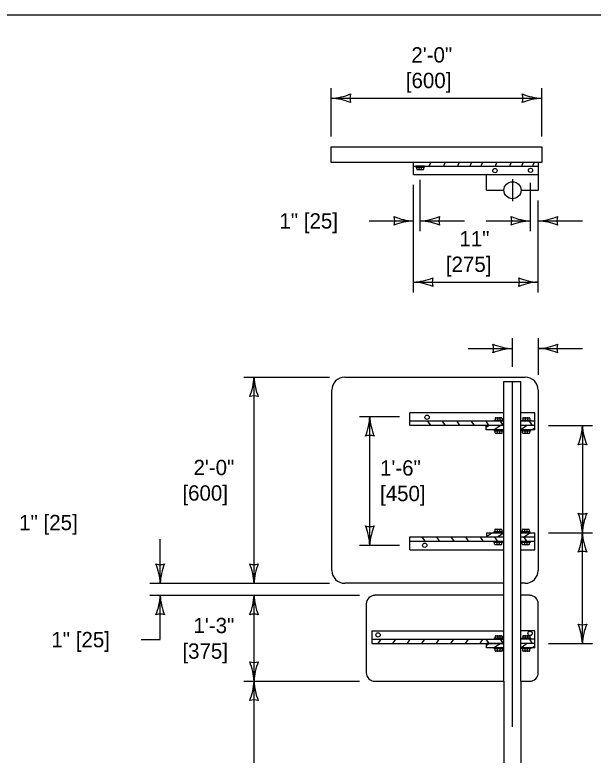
# Model space of a CAD drawing. Extents: x 49991.4 to 50021, y 49987.6 to 50011.4.
# Drawn here: x 50012.618 to 50014.882, y 49996.099 to 49998.999 of the extents above; entities that cross this region are included whole.
import ezdxf

# ---------------------------------------------------------------- set-up
doc = ezdxf.new("R2010")
doc.units = 0
for name, color, linetype in [('Level 1', 7, 'Continuous'), ('Level 2', 7, 'Continuous'), ('Level 3', 7, 'Continuous'), ('Level 4', 7, 'Continuous'), ('Level 5', 7, 'Continuous')]:
    doc.layers.add(name, color=color, linetype=linetype)

msp = doc.modelspace()

# ---------------------------------------------------------------- linework, layer by layer
at = {"layer": 'Level 1'}
for p, q in [((50014.1786, 49998.3732), (50014.1786, 49998.4206)), ((50014.2408, 49998.4065), (50014.2461, 49998.4206)), ((50014.2976, 49998.4065), (50014.3029, 49998.4206)), ((50014.3526, 49998.4065), (50014.358, 49998.4206)), ((50014.4006, 49998.4065), (50014.4059, 49998.4206)), ((50014.4435, 49998.4065), (50014.4489, 49998.4206)), ((50014.5003, 49998.4065), (50014.5057, 49998.4206)), ((50014.5554, 49998.4065), (50014.5607, 49998.4206)), ((50014.6033, 49998.4065), (50014.6087, 49998.4206)), ((50014.6464, 49998.4065), (50014.6518, 49998.4206)), ((50014.6668, 49998.4206), (50014.6668, 49998.3119)), ((50014.1786, 49998.4065), (50014.6668, 49998.4065)), ((50014.1913, 49998.3955), (50014.1913, 49998.4018)), ((50014.1939, 49998.3929), (50014.2165, 49998.3929)), ((50014.2005, 49998.3954), (50014.2005, 49998.4018)), ((50014.2097, 49998.3954), (50014.2097, 49998.4018)), ((50014.219, 49998.3955), (50014.219, 49998.4018)), ((50014.1786, 49998.3732), (50014.4642, 49998.3732)), ((50014.4642, 49998.3732), (50014.6659, 49998.3732)), ((50014.4642, 49998.3119), (50014.4642, 49998.3732)), ((50014.4642, 49998.3119), (50014.5331, 49998.3119)), ((50014.5996, 49998.3119), (50014.6668, 49998.3119)), ((50013.9097, 49997.5797), (50014.6163, 49997.5797)), ((50014.5327, 49996.3886), (50014.5327, 49997.563)), ((50014.5327, 49997.563), (50014.5992, 49997.563)), ((50014.5992, 49996.3886), (50014.5992, 49997.563)), ((50013.8593, 49996.8226), (50013.8593, 49997.5292)), ((50014.6668, 49997.5292), (50014.6668, 49996.8226)), ((50014.5316, 49997.4401), (50014.1645, 49997.4401)), ((50014.1645, 49997.3901), (50014.1645, 49997.4401)), ((50014.6535, 49997.4401), (50014.5993, 49997.4401)), ((50014.6535, 49997.3734), (50014.6535, 49997.4401)), ((50014.5316, 49997.4068), (50014.1645, 49997.4068)), ((50014.2341, 49997.4068), (50014.2454, 49997.3901)), ((50014.2911, 49997.4068), (50014.3023, 49997.3901)), ((50014.3479, 49997.4068), (50014.3591, 49997.3901)), ((50014.4048, 49997.4068), (50014.416, 49997.3901)), ((50014.4617, 49997.4068), (50014.473, 49997.3901)), ((50014.4981, 49997.4181), (50014.4981, 49997.4119)), ((50014.5005, 49997.4206), (50014.5232, 49997.4206)), ((50014.5006, 49997.4206), (50014.5232, 49997.4206)), ((50014.5072, 49997.4206), (50014.5072, 49997.4119)), ((50014.5165, 49997.4206), (50014.5165, 49997.4119)), ((50014.5186, 49997.4068), (50014.5298, 49997.3901)), ((50014.5191, 49997.406), (50014.5288, 49997.3916)), ((50014.5191, 49997.406), (50014.5288, 49997.3916)), ((50014.5257, 49997.4181), (50014.5257, 49997.4119)), ((50014.6535, 49997.4068), (50014.5992, 49997.4068)), ((50014.6064, 49997.4181), (50014.6064, 49997.4119)), ((50014.6088, 49997.4206), (50014.6315, 49997.4206)), ((50014.6089, 49997.4206), (50014.6315, 49997.4206)), ((50014.6155, 49997.4206), (50014.6155, 49997.4119)), ((50014.6248, 49997.4206), (50014.6248, 49997.4119)), ((50014.6324, 49997.4067), (50014.6435, 49997.3901)), ((50014.6324, 49997.4067), (50014.6425, 49997.3916)), ((50014.6324, 49997.4067), (50014.6425, 49997.3916)), ((50014.634, 49997.4181), (50014.634, 49997.4119)), ((50014.4639, 49997.3901), (50014.1645, 49997.3901)), ((50014.5316, 49997.3901), (50014.4639, 49997.3901)), ((50014.4639, 49997.384), (50014.473, 49997.3901)), ((50014.5322, 49997.3901), (50014.4639, 49997.3901)), ((50014.4639, 49997.3734), (50014.4639, 49997.39)), ((50014.5303, 49997.3734), (50014.4639, 49997.3734)), ((50014.4934, 49997.3734), (50014.5181, 49997.3901)), ((50014.6535, 49997.3901), (50014.5985, 49997.3901)), ((50014.6535, 49997.3901), (50014.5985, 49997.3901)), ((50014.6535, 49997.3901), (50014.5992, 49997.3901)), ((50014.5992, 49997.3749), (50014.6212, 49997.3899)), ((50014.6535, 49997.3734), (50014.5993, 49997.3734)), ((50014.6535, 49997.3901), (50014.5998, 49997.3901)), ((50014.6421, 49997.3734), (50014.6535, 49997.381)), ((50014.4989, 49997.3622), (50014.4989, 49997.3684)), ((50014.524, 49997.3596), (50014.5014, 49997.3596)), ((50014.5241, 49997.3596), (50014.5014, 49997.3596)), ((50014.5081, 49997.3596), (50014.5081, 49997.3684)), ((50014.5174, 49997.3596), (50014.5174, 49997.3684)), ((50014.5266, 49997.3622), (50014.5266, 49997.3684)), ((50014.6062, 49997.3621), (50014.6062, 49997.3683)), ((50014.6313, 49997.3595), (50014.6086, 49997.3595)), ((50014.6314, 49997.3595), (50014.6086, 49997.3595)), ((50014.6154, 49997.3595), (50014.6154, 49997.3683)), ((50014.6247, 49997.3595), (50014.6247, 49997.3683)), ((50014.6338, 49997.3621), (50014.6338, 49997.3683)), ((50014.4642, 49996.9704), (50014.4642, 49996.954)), ((50014.4642, 49996.9704), (50014.5309, 49996.9704)), ((50014.488, 49996.97), (50014.4642, 49996.954)), ((50014.4968, 49996.9817), (50014.4968, 49996.9756)), ((50014.4993, 49996.9843), (50014.522, 49996.9843)), ((50014.4994, 49996.9843), (50014.522, 49996.9843)), ((50014.506, 49996.9843), (50014.506, 49996.9756)), ((50014.532, 49996.9692), (50014.5095, 49996.9539)), ((50014.5153, 49996.9843), (50014.5153, 49996.9756)), ((50014.5245, 49996.9817), (50014.5245, 49996.9756)), ((50014.5993, 49996.9704), (50014.6535, 49996.9704)), ((50014.6041, 49996.9816), (50014.6041, 49996.9755)), ((50014.6066, 49996.9842), (50014.6293, 49996.9842)), ((50014.6066, 49996.9842), (50014.6293, 49996.9842)), ((50014.6373, 49996.9705), (50014.6128, 49996.9539)), ((50014.6132, 49996.9842), (50014.6132, 49996.9755)), ((50014.6225, 49996.9842), (50014.6225, 49996.9755)), ((50014.6317, 49996.9816), (50014.6317, 49996.9755)), ((50014.6535, 49996.9037), (50014.6535, 49996.9704)), ((50014.1645, 49996.9037), (50014.1645, 49996.9537)), ((50014.1645, 49996.9537), (50014.4642, 49996.9537)), ((50014.1645, 49996.937), (50014.5323, 49996.937)), ((50014.2117, 49996.9537), (50014.2227, 49996.9376)), ((50014.2686, 49996.9537), (50014.2796, 49996.9376)), ((50014.3254, 49996.9537), (50014.3364, 49996.9376)), ((50014.3824, 49996.9537), (50014.3933, 49996.9376)), ((50014.4393, 49996.9537), (50014.4502, 49996.9376)), ((50014.4393, 49996.9537), (50014.4502, 49996.9376)), ((50014.4642, 49996.9537), (50014.5323, 49996.9537)), ((50014.4961, 49996.9537), (50014.507, 49996.9376)), ((50014.4961, 49996.9537), (50014.507, 49996.9376)), ((50014.4961, 49996.9537), (50014.507, 49996.9376)), ((50014.4961, 49996.9537), (50014.507, 49996.9376)), ((50014.4961, 49996.9537), (50014.507, 49996.9376)), ((50014.4961, 49996.9537), (50014.507, 49996.9376)), ((50014.599, 49996.9537), (50014.6535, 49996.9537)), ((50014.599, 49996.9537), (50014.6523, 49996.9537)), ((50014.599, 49996.9537), (50014.6523, 49996.9537)), ((50014.599, 49996.9537), (50014.6513, 49996.9537)), ((50014.599, 49996.937), (50014.6523, 49996.937)), ((50014.599, 49996.937), (50014.6535, 49996.937)), ((50014.6099, 49996.9537), (50014.6212, 49996.937)), ((50014.6099, 49996.9537), (50014.6208, 49996.9376)), ((50014.6099, 49996.9537), (50014.6208, 49996.9376)), ((50014.4966, 49996.9258), (50014.4966, 49996.9319)), ((50014.5217, 49996.9232), (50014.4991, 49996.9232)), ((50014.5218, 49996.9232), (50014.4991, 49996.9232)), ((50014.5059, 49996.9232), (50014.5059, 49996.9319)), ((50014.5152, 49996.9232), (50014.5152, 49996.9319)), ((50014.5243, 49996.9258), (50014.5243, 49996.9319)), ((50014.6049, 49996.9258), (50014.6049, 49996.9319)), ((50014.63, 49996.9232), (50014.6074, 49996.9232)), ((50014.6301, 49996.9232), (50014.6074, 49996.9232)), ((50014.6142, 49996.9232), (50014.6142, 49996.9319)), ((50014.6235, 49996.9232), (50014.6235, 49996.9319)), ((50014.6326, 49996.9258), (50014.6326, 49996.9319)), ((50014.1645, 49996.9037), (50014.5317, 49996.9037)), ((50014.599, 49996.9037), (50014.6535, 49996.9037)), ((50014.5327, 49996.7722), (50013.9097, 49996.7722)), ((50014.6163, 49996.7722), (50014.5992, 49996.7722)), ((50014.5327, 49996.7251), (50014.0278, 49996.7251)), ((50014.6334, 49996.7251), (50014.5992, 49996.7251)), ((50013.9941, 49996.6914), (50013.9941, 49996.4223)), ((50014.667, 49996.4223), (50014.667, 49996.6914)), ((50014.0155, 49996.5865), (50014.5317, 49996.5865)), ((50014.0155, 49996.5865), (50014.0155, 49996.5366)), ((50014.4982, 49996.5645), (50014.4982, 49996.5583)), ((50014.5006, 49996.567), (50014.5233, 49996.567)), ((50014.5007, 49996.567), (50014.5233, 49996.567)), ((50014.5073, 49996.567), (50014.5073, 49996.5583)), ((50014.5166, 49996.567), (50014.5166, 49996.5583)), ((50014.5258, 49996.5645), (50014.5258, 49996.5583)), ((50014.6536, 49996.5865), (50014.5994, 49996.5865)), ((50014.6065, 49996.5645), (50014.6065, 49996.5583)), ((50014.6089, 49996.567), (50014.6316, 49996.567)), ((50014.609, 49996.567), (50014.6316, 49996.567)), ((50014.6156, 49996.567), (50014.6156, 49996.5583)), ((50014.6249, 49996.567), (50014.6249, 49996.5583)), ((50014.6341, 49996.5645), (50014.6341, 49996.5583)), ((50014.6536, 49996.5198), (50014.6536, 49996.5865)), ((50014.0155, 49996.5533), (50014.5323, 49996.5533)), ((50014.0155, 49996.5366), (50014.464, 49996.5366)), ((50014.0411, 49996.5366), (50014.0524, 49996.5533)), ((50014.098, 49996.5366), (50014.1093, 49996.5533)), ((50014.1549, 49996.5366), (50014.1662, 49996.5533)), ((50014.2117, 49996.5366), (50014.2231, 49996.5533)), ((50014.2686, 49996.5366), (50014.28, 49996.5533)), ((50014.3254, 49996.5366), (50014.3368, 49996.5533)), ((50014.3824, 49996.5366), (50014.3937, 49996.5533)), ((50014.4393, 49996.5366), (50014.4506, 49996.5533)), ((50014.4618, 49996.5533), (50014.4732, 49996.5366)), ((50014.5327, 49996.5366), (50014.464, 49996.5366)), ((50014.464, 49996.5305), (50014.4732, 49996.5366)), ((50014.464, 49996.5366), (50014.5323, 49996.5366)), ((50014.464, 49996.5198), (50014.464, 49996.5365)), ((50014.4965, 49996.5218), (50014.5182, 49996.5366)), ((50014.5186, 49996.5533), (50014.5298, 49996.5366)), ((50014.5186, 49996.5533), (50014.5288, 49996.5381)), ((50014.5192, 49996.5524), (50014.5288, 49996.5381)), ((50014.6536, 49996.5533), (50014.5992, 49996.5533)), ((50014.5992, 49996.5198), (50014.6216, 49996.5366)), ((50014.6536, 49996.5366), (50014.5992, 49996.5366)), ((50014.6536, 49996.5366), (50014.5999, 49996.5366)), ((50014.6325, 49996.5531), (50014.6436, 49996.5366)), ((50014.6325, 49996.5531), (50014.6426, 49996.5381)), ((50014.6325, 49996.5531), (50014.6436, 49996.5366)), ((50014.6536, 49996.5366), (50014.6436, 49996.5366)), ((50014.5327, 49996.5198), (50014.464, 49996.5198)), ((50014.499, 49996.5086), (50014.499, 49996.5148)), ((50014.5241, 49996.5061), (50014.5015, 49996.5061)), ((50014.5242, 49996.5061), (50014.5015, 49996.5061)), ((50014.5082, 49996.5061), (50014.5082, 49996.5148)), ((50014.5175, 49996.5061), (50014.5175, 49996.5148)), ((50014.5267, 49996.5086), (50014.5267, 49996.5148)), ((50014.6536, 49996.5198), (50014.5992, 49996.5198)), ((50014.6063, 49996.5085), (50014.6063, 49996.5147)), ((50014.6314, 49996.506), (50014.6087, 49996.506)), ((50014.6314, 49996.506), (50014.6087, 49996.506)), ((50014.6155, 49996.506), (50014.6155, 49996.5147)), ((50014.6248, 49996.506), (50014.6248, 49996.5147)), ((50014.6339, 49996.5085), (50014.6339, 49996.5147)), ((50014.6422, 49996.5198), (50014.6536, 49996.5275)), ((50014.0278, 49996.3886), (50014.5327, 49996.3886)), ((50014.5327, 49996.3886), (50014.5327, 49994.5009)), ((50014.5992, 49996.3886), (50014.5992, 49994.5009)), ((50014.5992, 49996.3886), (50014.6334, 49996.3886))]:
    msp.add_line(p, q, dxfattribs=at)
for points in [[(49999.3835, 49998.9992), (50016.7501, 49998.9992), (50016.7501, 49987.7988), (49999.3835, 49987.7988)], [(50014.6809, 49998.4822), (50014.6809, 49998.4206), (50013.8568, 49998.4206), (50013.8568, 49998.4822)], [(50014.1886, 49998.4065), (50014.1886, 49998.4018), (50014.2214, 49998.4018), (50014.2214, 49998.4065)], [(50014.4953, 49997.407), (50014.4953, 49997.4117), (50014.5282, 49997.4117), (50014.5282, 49997.407)], [(50014.6036, 49997.407), (50014.6036, 49997.4117), (50014.6365, 49997.4117), (50014.6365, 49997.407)], [(50014.5293, 49997.3732), (50014.5293, 49997.3686), (50014.4964, 49997.3686), (50014.4964, 49997.3732)], [(50014.6366, 49997.3731), (50014.6366, 49997.3685), (50014.6037, 49997.3685), (50014.6037, 49997.3731)], [(50014.4941, 49996.9707), (50014.4941, 49996.9754), (50014.5269, 49996.9754), (50014.5269, 49996.9707)], [(50014.6013, 49996.9706), (50014.6013, 49996.9753), (50014.6342, 49996.9753), (50014.6342, 49996.9706)], [(50014.527, 49996.9368), (50014.527, 49996.9321), (50014.4942, 49996.9321), (50014.4942, 49996.9368)], [(50014.6353, 49996.9368), (50014.6353, 49996.9321), (50014.6025, 49996.9321), (50014.6025, 49996.9368)], [(50014.4954, 49996.5535), (50014.4954, 49996.5581), (50014.5283, 49996.5581), (50014.5283, 49996.5535)], [(50014.6037, 49996.5535), (50014.6037, 49996.5581), (50014.6366, 49996.5581), (50014.6366, 49996.5535)], [(50014.5294, 49996.5196), (50014.5294, 49996.515), (50014.4965, 49996.515), (50014.4965, 49996.5196)], [(50014.6367, 49996.5196), (50014.6367, 49996.5149), (50014.6038, 49996.5149), (50014.6038, 49996.5196)]]:
    msp.add_lwpolyline(points, close=True, dxfattribs=at)
for centre, radius in [((50014.4977, 49998.3891), 0.00843), ((50014.6369, 49998.39), 0.00843), ((50014.5664, 49998.3119), 0.0333), ((50014.2322, 49997.4225), 0.00843), ((50014.2229, 49996.9214), 0.00843), ((50014.04, 49996.5701), 0.00843), ((50014.6352, 49996.576), 0.00843)]:
    msp.add_circle(centre, radius, dxfattribs=at)
for centre, radius, start, end in [((50014.1939, 49998.3954), 0.00257, 180, 270), ((50014.198, 49998.3954), 0.00257, 270, 0), ((50014.2031, 49998.3954), 0.00257, 180, 270), ((50014.2072, 49998.3954), 0.00257, 270, 0), ((50014.2123, 49998.3954), 0.00257, 180, 270), ((50014.2164, 49998.3954), 0.00257, 270, 0), ((50013.9097, 49997.5292), 0.0505, 90, 180), ((50014.6163, 49997.5292), 0.0505, 0, 90), ((50014.5007, 49997.4181), 0.00257, 90, 180), ((50014.5047, 49997.4181), 0.00257, 0, 90), ((50014.5099, 49997.4181), 0.00257, 90, 180), ((50014.5139, 49997.4181), 0.00257, 0, 90), ((50014.5191, 49997.4181), 0.00257, 90, 180), ((50014.5231, 49997.4181), 0.00257, 0, 90), ((50014.609, 49997.4181), 0.00257, 90, 180), ((50014.613, 49997.4181), 0.00257, 0, 90), ((50014.6182, 49997.4181), 0.00257, 90, 180), ((50014.6222, 49997.4181), 0.00257, 0, 90), ((50014.6274, 49997.4181), 0.00257, 90, 180), ((50014.6314, 49997.4181), 0.00257, 0, 90), ((50014.5015, 49997.3622), 0.00257, 180, 270), ((50014.5056, 49997.3622), 0.00257, 270, 0), ((50014.5107, 49997.3622), 0.00257, 180, 270), ((50014.5148, 49997.3622), 0.00257, 270, 0), ((50014.5199, 49997.3622), 0.00257, 180, 270), ((50014.524, 49997.3622), 0.00257, 270, 0), ((50014.6087, 49997.3621), 0.00257, 180, 270), ((50014.6128, 49997.3621), 0.00257, 270, 0), ((50014.618, 49997.3621), 0.00257, 180, 270), ((50014.622, 49997.3621), 0.00257, 270, 0), ((50014.6272, 49997.3621), 0.00257, 180, 270), ((50014.6312, 49997.3621), 0.00257, 270, 0), ((50014.4994, 49996.9818), 0.00257, 90, 180), ((50014.5035, 49996.9818), 0.00257, 0, 90), ((50014.5086, 49996.9818), 0.00257, 90, 180), ((50014.5127, 49996.9818), 0.00257, 0, 90), ((50014.5178, 49996.9818), 0.00257, 90, 180), ((50014.5219, 49996.9818), 0.00257, 0, 90), ((50014.6067, 49996.9817), 0.00257, 90, 180), ((50014.6107, 49996.9817), 0.00257, 0, 90), ((50014.6159, 49996.9817), 0.00257, 90, 180), ((50014.6199, 49996.9817), 0.00257, 0, 90), ((50014.6251, 49996.9817), 0.00257, 90, 180), ((50014.6292, 49996.9817), 0.00257, 0, 90), ((50014.4992, 49996.9257), 0.00257, 180, 270), ((50014.5033, 49996.9257), 0.00257, 270, 0), ((50014.5084, 49996.9257), 0.00257, 180, 270), ((50014.5125, 49996.9257), 0.00257, 270, 0), ((50014.5176, 49996.9257), 0.00257, 180, 270), ((50014.5217, 49996.9257), 0.00257, 270, 0), ((50014.6075, 49996.9257), 0.00257, 180, 270), ((50014.6116, 49996.9257), 0.00257, 270, 0), ((50014.6167, 49996.9257), 0.00257, 180, 270), ((50014.6208, 49996.9257), 0.00257, 270, 0), ((50014.6259, 49996.9257), 0.00257, 180, 270), ((50014.63, 49996.9257), 0.00257, 270, 0), ((50013.9097, 49996.8226), 0.0505, 180, 270), ((50014.6163, 49996.8226), 0.0505, 270, 0), ((50014.0278, 49996.6914), 0.0336, 90, 180), ((50014.6334, 49996.6914), 0.0336, 0, 90), ((50014.5008, 49996.5645), 0.00257, 90, 180), ((50014.5048, 49996.5645), 0.00257, 0, 90), ((50014.51, 49996.5645), 0.00257, 90, 180), ((50014.514, 49996.5645), 0.00257, 0, 90), ((50014.5192, 49996.5645), 0.00257, 90, 180), ((50014.5232, 49996.5645), 0.00257, 0, 90), ((50014.6091, 49996.5645), 0.00257, 90, 180), ((50014.6131, 49996.5645), 0.00257, 0, 90), ((50014.6183, 49996.5645), 0.00257, 90, 180), ((50014.6223, 49996.5645), 0.00257, 0, 90), ((50014.6275, 49996.5645), 0.00257, 90, 180), ((50014.6315, 49996.5645), 0.00257, 0, 90), ((50014.5016, 49996.5086), 0.00257, 180, 270), ((50014.5057, 49996.5086), 0.00257, 270, 0), ((50014.5108, 49996.5086), 0.00257, 180, 270), ((50014.5149, 49996.5086), 0.00257, 270, 0), ((50014.52, 49996.5086), 0.00257, 180, 270), ((50014.5241, 49996.5086), 0.00257, 270, 0), ((50014.6088, 49996.5085), 0.00257, 180, 270), ((50014.6129, 49996.5085), 0.00257, 270, 0), ((50014.6181, 49996.5085), 0.00257, 180, 270), ((50014.6221, 49996.5085), 0.00257, 270, 0), ((50014.6273, 49996.5085), 0.00257, 180, 270), ((50014.6313, 49996.5085), 0.00257, 270, 0), ((50014.0278, 49996.4223), 0.0336, 180, 270), ((50014.6334, 49996.4223), 0.0336, 270, 0)]:
    msp.add_arc(centre, radius, start, end, dxfattribs=at)
at = {"layer": 'Level 3'}
for p, q in [((50013.8568, 49998.5222), (50013.8568, 49998.7122)), ((50014.6809, 49998.5222), (50014.6809, 49998.7122)), ((50013.8568, 49998.6722), (50014.6809, 49998.6722)), ((50014.1786, 49997.9119), (50014.1786, 49998.3332)), ((50014.2052, 49998.1519), (50014.2052, 49998.3528)), ((50014.6372, 49998.1519), (50014.6372, 49998.3416)), ((50014.6668, 49997.9119), (50014.6668, 49998.2719)), ((50014.0052, 49998.1919), (50014.1786, 49998.1919)), ((50014.2052, 49998.1919), (50014.3786, 49998.1919)), ((50014.4638, 49998.1919), (50014.6372, 49998.1919)), ((50014.6668, 49998.1919), (50014.8402, 49998.1919)), ((50014.1786, 49997.9519), (50014.6668, 49997.9519)), ((50014.566, 49997.6197), (50014.566, 49997.732)), ((50014.6668, 49997.732), (50014.6668, 49997.5892)), ((50014.3926, 49997.692), (50014.566, 49997.692)), ((50014.6668, 49997.692), (50014.8402, 49997.692)), ((50013.5146, 49997.5797), (50013.8497, 49997.5797)), ((50013.5546, 49996.7722), (50013.5546, 49997.5797)), ((50013.9678, 49997.4251), (50014.1245, 49997.4251)), ((50014.0078, 49996.9212), (50014.0078, 49997.4251)), ((50014.7068, 49997.3901), (50014.8802, 49997.3901)), ((50014.8402, 49997.3901), (50014.8402, 49996.9704)), ((50014.7068, 49996.9704), (50014.8802, 49996.9704)), ((50014.8402, 49996.5366), (50014.8402, 49996.9704)), ((50013.1874, 49996.7722), (50013.1874, 49996.9456)), ((50013.9678, 49996.9212), (50014.1245, 49996.9212)), ((50013.1474, 49996.7722), (50013.8497, 49996.7722)), ((50013.1474, 49996.7251), (50013.9678, 49996.7251)), ((50013.1874, 49996.5517), (50013.1874, 49996.7251)), ((50013.5546, 49996.3886), (50013.5546, 49996.7251)), ((50013.1125, 49996.5517), (50013.1874, 49996.5517)), ((50014.7071, 49996.5366), (50014.8802, 49996.5366)), ((50013.5146, 49996.3886), (50013.9678, 49996.3886)), ((50013.5546, 49994.5009), (50013.5546, 49996.3886))]:
    msp.add_line(p, q, dxfattribs=at)
for centre, radius, start, end in [((50013.8453, 49998.9049), 0.233, 272.8273, 292.0772), ((50013.985, 49998.6722), 0.0548, 162.1388, 197.8612), ((50014.6901, 49998.8943), 0.2223, 247.456, 267.6395), ((50014.5527, 49998.6722), 0.0548, 342.1388, 17.8612), ((50013.8476, 49998.45), 0.2223, 67.456, 87.6395), ((50014.6924, 49998.4395), 0.233, 92.8273, 112.0772), ((50014.1878, 49998.414), 0.2223, 247.456, 267.6395), ((50014.0504, 49998.1919), 0.0548, 342.1388, 17.8612), ((50014.1901, 49997.9592), 0.233, 92.8273, 112.0772), ((50014.1937, 49998.4246), 0.233, 272.8273, 292.0772), ((50014.196, 49997.9697), 0.2223, 67.456, 87.6395), ((50014.3334, 49998.1919), 0.0548, 162.1388, 197.8612), ((50014.6464, 49998.414), 0.2223, 247.456, 267.6395), ((50014.509, 49998.1919), 0.0548, 342.1388, 17.8612), ((50014.6487, 49997.9592), 0.233, 92.8273, 112.0772), ((50014.6553, 49998.4246), 0.233, 272.8273, 292.0772), ((50014.6576, 49997.9697), 0.2223, 67.456, 87.6395), ((50014.795, 49998.1919), 0.0548, 162.1388, 197.8612), ((50014.1671, 49998.1846), 0.233, 272.8273, 292.0772), ((50014.1694, 49997.7297), 0.2223, 67.456, 87.6395), ((50014.3068, 49997.9519), 0.0548, 162.1388, 197.8612), ((50014.676, 49998.174), 0.2223, 247.456, 267.6395), ((50014.5386, 49997.9519), 0.0548, 342.1388, 17.8612), ((50014.6783, 49997.7192), 0.233, 92.8273, 112.0772), ((50014.5752, 49997.9141), 0.2223, 247.456, 267.6395), ((50014.4378, 49997.692), 0.0548, 342.1388, 17.8612), ((50014.5775, 49997.4593), 0.233, 92.8273, 112.0772), ((50014.6553, 49997.9247), 0.233, 272.8273, 292.0772), ((50014.6576, 49997.4699), 0.2223, 67.456, 87.6395), ((50014.795, 49997.692), 0.0548, 162.1388, 197.8612), ((50013.3325, 49997.5889), 0.2223, 337.456, 357.6395), ((50013.7873, 49997.5912), 0.233, 182.8273, 202.0772), ((50013.5546, 49997.4515), 0.0548, 72.1388, 107.8612), ((50013.7857, 49997.4343), 0.2223, 337.456, 357.6395), ((50014.2405, 49997.4366), 0.233, 182.8273, 202.0772), ((50014.6181, 49997.3993), 0.2223, 337.456, 357.6395), ((50015.0729, 49997.4016), 0.233, 182.8273, 202.0772), ((50014.0078, 49997.2969), 0.0548, 72.1388, 107.8612), ((50014.8402, 49997.2619), 0.0548, 72.1388, 107.8612), ((50014.8402, 49997.0986), 0.0548, 252.1388, 287.8612), ((50014.6075, 49996.9589), 0.233, 2.8273, 22.0772), ((50015.0623, 49996.9612), 0.2223, 157.456, 177.6395), ((50014.0078, 49997.0494), 0.0548, 252.1388, 287.8612), ((50013.7751, 49996.9097), 0.233, 2.8273, 22.0772), ((50014.2299, 49996.912), 0.2223, 157.456, 177.6395), ((50014.6181, 49996.9796), 0.2223, 337.456, 357.6395), ((50015.0729, 49996.9819), 0.233, 182.8273, 202.0772), ((50014.8402, 49996.8422), 0.0548, 72.1388, 107.8612), ((50013.1874, 49996.9004), 0.0548, 252.1388, 287.8612), ((50012.9547, 49996.7607), 0.233, 2.8273, 22.0772), ((50013.4095, 49996.763), 0.2223, 157.456, 177.6395), ((50013.5546, 49996.9004), 0.0548, 252.1388, 287.8612), ((50013.3219, 49996.7607), 0.233, 2.8273, 22.0772), ((50013.7767, 49996.763), 0.2223, 157.456, 177.6395), ((50012.9653, 49996.7343), 0.2223, 337.456, 357.6395), ((50013.4201, 49996.7366), 0.233, 182.8273, 202.0772), ((50013.3325, 49996.7343), 0.2223, 337.456, 357.6395), ((50013.7873, 49996.7366), 0.233, 182.8273, 202.0772), ((50013.1874, 49996.5969), 0.0548, 72.1388, 107.8612), ((50013.5546, 49996.5969), 0.0548, 72.1388, 107.8612), ((50014.8402, 49996.6648), 0.0548, 252.1388, 287.8612), ((50014.6075, 49996.5251), 0.233, 2.8273, 22.0772), ((50015.0623, 49996.5274), 0.2223, 157.456, 177.6395), ((50013.5546, 49996.5168), 0.0548, 252.1388, 287.8612), ((50013.3219, 49996.3771), 0.233, 2.8273, 22.0772), ((50013.7767, 49996.3794), 0.2223, 157.456, 177.6395), ((50013.3325, 49996.3978), 0.2223, 337.456, 357.6395), ((50013.7873, 49996.4001), 0.233, 182.8273, 202.0772), ((50013.5546, 49996.2604), 0.0548, 72.1388, 107.8612)]:
    msp.add_arc(centre, radius, start, end, dxfattribs=at)
at = {"layer": 'Level 4'}
msp.add_line((50014.566, 49996.2095), (50014.566, 49997.563), dxfattribs=at)
at = {"layer": 'Level 5'}
msp.add_line((50014.5663, 49998.3552), (50014.5663, 49998.2687), dxfattribs=at)

# ---------------------------------------------------------------- texts
at = {"layer": 'Level 2'}
for s, p in [('2\'-0"', (50014.1705, 49998.8122)), ('[600]', (50014.1488, 49998.7122)), ('1" [25]', (50013.6541, 49998.1619)), ('11"', (50014.3585, 49998.0919)), ('[275]', (50014.3055, 49997.9919)), ('2\'-0"', (50013.3177, 49997.196)), ('1\'-6"', (50014.0478, 49997.1941)), ('[600]', (50013.2742, 49997.096)), ('[450]', (50014.0478, 49997.0941)), ('1" [25]', (50012.6352, 49996.9803)), ('1\'-3"', (50013.3177, 49996.5769)), ('1" [25]', (50012.7614, 49996.5217)), ('[375]', (50013.2742, 49996.4768))]:
    msp.add_text(s, height=0.06, dxfattribs=at).set_placement(p)

doc.saveas('drawing.dxf')
